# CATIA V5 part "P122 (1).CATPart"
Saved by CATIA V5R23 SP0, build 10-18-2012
Part number: 05-LICP-T02-E-S11-P122 (1)
Definition: butee a aiguilles
Description: butee_a_aiguilles_ax_5_40_60_01
Bounding box of the stored display mesh (mm): x 3.222 to 4.4, y -29.191 to 29.191, z -29.2 to 29.2
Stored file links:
  C:\wamp\www\COURS\CONCEPTION GMP1\TITRE 02-SEMESTRE 2\03-TP7-PRESSE MECANIQUE\eleve\P122 (1).CATPart
  P:\etudiants\lpro\ProjetsTUT-LP-2005\Deletré Makowski Theallier\05-LICP-T02 - Assemblage Presse Mécanique\- Presse Mecanique (Motion CATIA 2004+).CATProduct
  C:\wamp\www\COURS\CONCEPTION GMP1\TITRE 02-SEMESTRE 2\03-TP7-PRESSE MECANIQUE\eleve\05-LICP-T02-E-S11-P122 (2).CATPart
  C:\wamp\www\COURS\CONCEPTION GMP1\TITRE 02-SEMESTRE 2\03-TP7-PRESSE MECANIQUE\eleve\P122 (4).CATPart
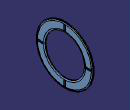
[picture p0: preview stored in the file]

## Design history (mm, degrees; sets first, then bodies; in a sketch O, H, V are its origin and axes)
Set1
  DatumSurface1: linked copy from another document
Set2
  Plane1: type Offset, RefPlane DatumSurface1, Offset 5
Body1 (main body)
  Solid1: solid without history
